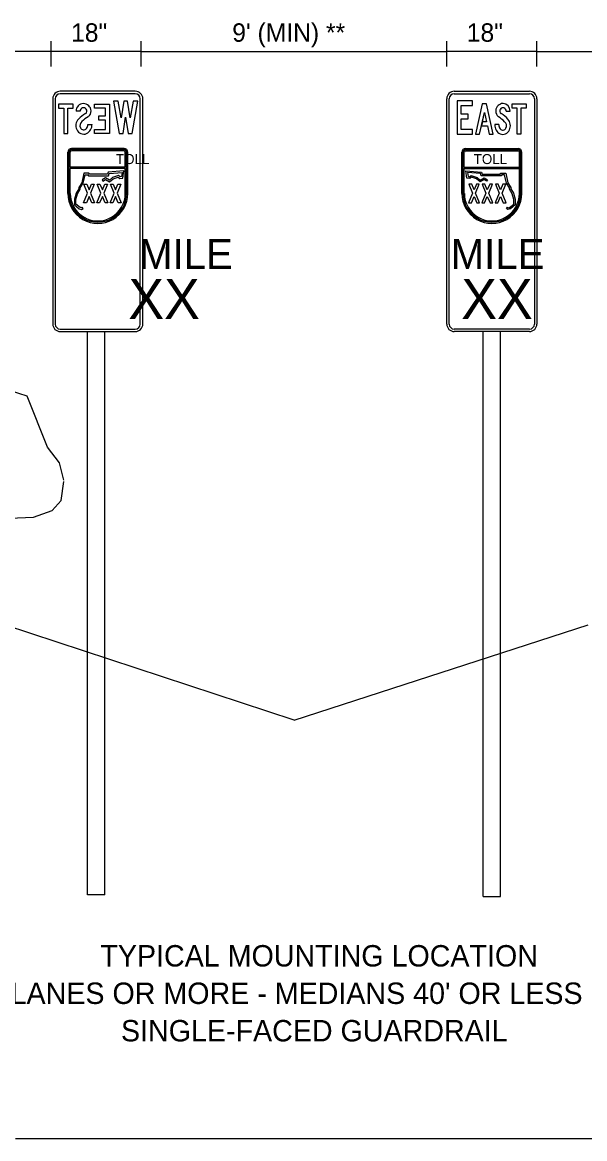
# Model space of a CAD drawing. Extents: x 57428 to 58066, y 11696 to 12105.
# Drawn here: x 57710.6 to 57796, y 11934.3 to 12103.9 of the extents above; entities that cross this region are included whole.
import ezdxf

# ---------------------------------------------------------------- set-up
doc = ezdxf.new("R2010")
doc.units = 0
for name, color, linetype in [('62', 7, 'Continuous'), ('DimLines_dp', 7, 'Continuous'), ('NonPlottingEle_dp', 7, 'Continuous'), ('SignPanel', 7, 'Continuous'), ('TextMisc', 7, 'Continuous'), ('TextTables', 7, 'Continuous'), ('XSGrdLine_ex', 7, 'Continuous')]:
    doc.layers.add(name, color=color, linetype=linetype)

msp = doc.modelspace()

# ---------------------------------------------------------------- linework, layer by layer
at = {"layer": '62'}
msp.add_lwpolyline([(57716.92, 12034.31), (57716.22, 12036.91), (57714.42, 12039.32), (57711.32, 12047.07), (57706.22, 12048.67), (57702.51, 12048.17), (57697.71, 12040.32), (57696.21, 12037.11), (57696.01, 12033.61), (57697.21, 12030.61), (57700.31, 12028.9), (57706.22, 12028.4), (57712.32, 12028.7), (57715.12, 12029.7), (57716.52, 12031.21), (57716.92, 12034.11)], dxfattribs=at)
at = {"layer": 'DimLines_dp'}
for p, q in [((57714.97, 12097.15), (57714.97, 12100.98)), ((57728.65, 12097.15), (57728.65, 12100.98)), ((57775.06, 12097.15), (57775.06, 12100.98)), ((57788.75, 12097.15), (57788.75, 12100.98)), ((57714.97, 12099.43), (57645.43, 12099.43)), ((57728.65, 12099.43), (57714.97, 12099.43)), ((57728.65, 12099.43), (57775.06, 12099.43)), ((57788.75, 12099.43), (57775.06, 12099.43)), ((57788.75, 12099.43), (57858.29, 12099.43))]:
    msp.add_line(p, q, dxfattribs=at)
at = {"layer": 'NonPlottingEle_dp'}
for p, q in [((57720.48, 12008.18), (57720.48, 12056.87)), ((57723.14, 12007.3), (57723.14, 12056.87)), ((57780.58, 12007.16), (57780.58, 12056.87)), ((57783.24, 12008.02), (57783.24, 12056.87)), ((57720.48, 11971.28), (57720.48, 12008.18)), ((57783.24, 11971.03), (57783.24, 12008.02)), ((57723.14, 11971.28), (57723.14, 12007.3)), ((57780.58, 11971.03), (57780.58, 12007.16)), ((57723.14, 11971.28), (57720.48, 11971.28)), ((57780.58, 11971.03), (57783.24, 11971.03))]:
    msp.add_line(p, q, dxfattribs=at)
at = {"layer": 'SignPanel'}
for p, q in [((57719.37, 12090.36), (57718.75, 12090.36)), ((57719.37, 12090.36), (57718.75, 12090.36)), ((57719.37, 12090.36), (57718.75, 12090.36)), ((57784.1, 12090.36), (57784.68, 12090.36)), ((57784.1, 12090.36), (57784.68, 12090.36)), ((57784.1, 12090.36), (57784.68, 12090.36)), ((57720.56, 12088.35), (57721.19, 12088.35)), ((57720.56, 12088.35), (57721.19, 12088.35)), ((57720.56, 12088.35), (57721.19, 12088.35)), ((57782.96, 12088.32), (57782.37, 12088.32)), ((57782.96, 12088.32), (57782.37, 12088.32)), ((57782.96, 12088.32), (57782.37, 12088.32)), ((57717.5, 12077.85), (57717.5, 12084.13)), ((57717.69, 12077.85), (57717.69, 12084.13)), ((57717.88, 12081.85), (57717.88, 12084.13)), ((57726.05, 12084.7), (57718.07, 12084.7)), ((57726.05, 12084.51), (57718.07, 12084.51)), ((57726.05, 12084.32), (57718.07, 12084.32)), ((57726.24, 12081.85), (57726.24, 12084.13)), ((57726.43, 12077.85), (57726.43, 12084.13)), ((57726.62, 12077.85), (57726.62, 12084.13)), ((57777.35, 12077.85), (57777.35, 12084.13)), ((57777.54, 12077.85), (57777.54, 12084.13)), ((57777.72, 12081.85), (57777.72, 12084.13)), ((57777.92, 12084.7), (57785.9, 12084.7)), ((57777.92, 12084.51), (57785.9, 12084.51)), ((57777.92, 12084.32), (57785.9, 12084.32)), ((57786.09, 12081.85), (57786.09, 12084.13)), ((57786.28, 12077.85), (57786.28, 12084.13)), ((57786.47, 12077.85), (57786.47, 12084.13)), ((57726.24, 12081.85), (57717.88, 12081.85)), ((57717.88, 12077.85), (57717.88, 12081.66)), ((57726.24, 12081.66), (57717.88, 12081.66)), ((57719.95, 12080.92), (57719.62, 12079.49)), ((57719.83, 12079.4), (57720.13, 12080.69)), ((57720.68, 12080.92), (57719.95, 12080.92)), ((57720.13, 12080.69), (57720.56, 12080.69)), ((57720.56, 12080.69), (57720.66, 12080.53)), ((57720.66, 12080.53), (57723.67, 12080.53)), ((57720.79, 12080.76), (57720.68, 12080.92)), ((57723.52, 12080.76), (57720.79, 12080.76)), ((57723.65, 12081.11), (57723.52, 12080.76)), ((57726.03, 12081.29), (57723.65, 12081.11)), ((57723.67, 12080.53), (57723.81, 12080.89)), ((57723.81, 12080.89), (57725.76, 12081.04)), ((57725.2, 12080.6), (57724.28, 12080.3)), ((57724.77, 12080.95), (57724.77, 12080.95)), ((57725.47, 12080.38), (57725.2, 12080.6)), ((57725.76, 12081.04), (57725.66, 12080.41)), ((57725.86, 12080.2), (57726.03, 12081.29)), ((57726.24, 12077.85), (57726.24, 12081.66)), ((57777.72, 12081.85), (57786.09, 12081.85)), ((57777.72, 12077.85), (57777.72, 12081.66)), ((57777.72, 12081.66), (57786.09, 12081.66)), ((57778.11, 12080.2), (57777.94, 12081.29)), ((57777.94, 12081.29), (57780.32, 12081.11)), ((57780.16, 12080.89), (57778.21, 12081.04)), ((57778.21, 12081.04), (57778.31, 12080.41)), ((57778.5, 12080.38), (57778.77, 12080.6)), ((57778.77, 12080.6), (57779.69, 12080.3)), ((57779.2, 12080.95), (57779.2, 12080.95)), ((57780.3, 12080.53), (57780.16, 12080.89)), ((57783.31, 12080.53), (57780.3, 12080.53)), ((57780.32, 12081.11), (57780.45, 12080.76)), ((57780.45, 12080.76), (57783.18, 12080.76)), ((57783.18, 12080.76), (57783.29, 12080.92)), ((57783.29, 12080.92), (57784.02, 12080.92)), ((57783.41, 12080.69), (57783.31, 12080.53)), ((57783.84, 12080.69), (57783.41, 12080.69)), ((57784.14, 12079.4), (57783.84, 12080.69)), ((57784.02, 12080.92), (57784.35, 12079.49)), ((57786.09, 12077.85), (57786.09, 12081.66)), ((57719.62, 12079.49), (57719.16, 12078.76)), ((57719.39, 12078.69), (57719.83, 12079.4)), ((57723.22, 12080.24), (57722.72, 12079.9)), ((57722.72, 12079.9), (57722.85, 12079.71)), ((57722.85, 12079.71), (57723.23, 12079.97)), ((57723.83, 12079.88), (57723.22, 12080.24)), ((57723.23, 12079.97), (57723.86, 12079.6)), ((57724.28, 12080.3), (57723.83, 12079.88)), ((57723.86, 12079.6), (57724.4, 12080.1)), ((57724.4, 12080.1), (57725.15, 12080.34)), ((57725.15, 12080.34), (57725.4, 12080.15)), ((57725.4, 12080.15), (57725.86, 12080.2)), ((57725.66, 12080.41), (57725.47, 12080.38)), ((57778.56, 12080.15), (57778.11, 12080.2)), ((57778.31, 12080.41), (57778.5, 12080.38)), ((57778.81, 12080.34), (57778.56, 12080.15)), ((57779.57, 12080.1), (57778.81, 12080.34)), ((57780.11, 12079.6), (57779.57, 12080.1)), ((57779.69, 12080.3), (57780.14, 12079.88)), ((57780.74, 12079.97), (57780.11, 12079.6)), ((57780.14, 12079.88), (57780.75, 12080.24)), ((57781.12, 12079.71), (57780.74, 12079.97)), ((57780.75, 12080.24), (57781.25, 12079.9)), ((57781.25, 12079.9), (57781.12, 12079.71)), ((57784.58, 12078.69), (57784.14, 12079.4)), ((57784.35, 12079.49), (57784.81, 12078.76)), ((57718.75, 12077.9), (57718.5, 12076.98)), ((57718.73, 12076.95), (57718.97, 12077.81)), ((57719.16, 12078.57), (57718.75, 12077.9)), ((57718.97, 12077.81), (57719.39, 12078.51)), ((57719.16, 12078.76), (57719.16, 12078.57)), ((57719.39, 12078.51), (57719.39, 12078.69)), ((57784.58, 12078.51), (57784.58, 12078.69)), ((57785, 12077.81), (57784.58, 12078.51)), ((57784.81, 12078.76), (57784.81, 12078.57)), ((57784.81, 12078.57), (57785.22, 12077.9)), ((57785.24, 12076.95), (57785, 12077.81)), ((57785.22, 12077.9), (57785.47, 12076.98)), ((57718.5, 12076.98), (57718.5, 12076.12)), ((57718.5, 12076.12), (57719.25, 12075.5)), ((57718.73, 12076.22), (57718.73, 12076.95)), ((57719.36, 12075.71), (57718.73, 12076.22)), ((57719.25, 12075.5), (57719.61, 12075.41)), ((57719.56, 12075.66), (57719.36, 12075.71)), ((57719.71, 12075.76), (57719.56, 12075.66)), ((57719.61, 12075.41), (57719.84, 12075.57)), ((57719.84, 12075.57), (57719.71, 12075.76)), ((57784.13, 12075.57), (57784.26, 12075.76)), ((57784.36, 12075.41), (57784.13, 12075.57)), ((57784.26, 12075.76), (57784.41, 12075.66)), ((57784.72, 12075.5), (57784.36, 12075.41)), ((57784.41, 12075.66), (57784.61, 12075.71)), ((57784.61, 12075.71), (57785.24, 12076.22)), ((57785.47, 12076.12), (57784.72, 12075.5)), ((57785.24, 12076.22), (57785.24, 12076.95)), ((57785.47, 12076.98), (57785.47, 12076.12))]:
    msp.add_line(p, q, dxfattribs=at)
for points in [[(57727.76, 12093.37), (57716.36, 12093.37)], [(57727.76, 12092.99), (57716.36, 12092.99)], [(57776.2, 12093.37), (57787.61, 12093.37)], [(57776.2, 12092.99), (57787.61, 12092.99)], [(57715.22, 12092.23), (57715.22, 12058.01)], [(57715.6, 12092.23), (57715.6, 12058.01)], [(57728.52, 12058.01), (57728.52, 12092.23)], [(57728.9, 12058.01), (57728.9, 12092.23)], [(57775.06, 12058.01), (57775.06, 12092.23)], [(57775.44, 12058.01), (57775.44, 12092.23)], [(57788.37, 12092.23), (57788.37, 12058.01)], [(57788.75, 12092.23), (57788.75, 12058.01)], [(57716.36, 12057.25), (57727.76, 12057.25)], [(57716.36, 12056.87), (57727.76, 12056.87)], [(57787.61, 12057.25), (57776.2, 12057.25)], [(57787.61, 12056.87), (57776.2, 12056.87)]]:
    msp.add_lwpolyline(points, dxfattribs=at)
for points in [[(57717.51, 12090.81), (57718.33, 12090.81), (57718.33, 12091.44), (57716.07, 12091.44), (57716.07, 12090.81), (57716.89, 12090.81), (57716.89, 12086.94), (57717.51, 12086.94)], [(57717.51, 12090.81), (57718.33, 12090.81), (57718.33, 12091.44), (57716.07, 12091.44), (57716.07, 12090.81), (57716.89, 12090.81), (57716.89, 12086.94), (57717.51, 12086.94)], [(57717.51, 12090.81), (57718.33, 12090.81), (57718.33, 12091.44), (57716.07, 12091.44), (57716.07, 12090.81), (57716.89, 12090.81), (57716.89, 12086.94), (57717.51, 12086.94)], [(57723.21, 12087.57), (57723.21, 12089.01), (57722.24, 12089.01), (57722.24, 12089.64), (57723.21, 12089.64), (57723.21, 12090.81), (57721.57, 12090.81), (57721.57, 12091.44), (57723.84, 12091.44), (57723.84, 12086.94), (57721.57, 12086.94), (57721.57, 12087.57)], [(57723.21, 12087.57), (57723.21, 12089.01), (57722.24, 12089.01), (57722.24, 12089.64), (57723.21, 12089.64), (57723.21, 12090.81), (57721.57, 12090.81), (57721.57, 12091.44), (57723.84, 12091.44), (57723.84, 12086.94), (57721.57, 12086.94), (57721.57, 12087.57)], [(57723.21, 12087.57), (57723.21, 12089.01), (57722.24, 12089.01), (57722.24, 12089.64), (57723.21, 12089.64), (57723.21, 12090.81), (57721.57, 12090.81), (57721.57, 12091.44), (57723.84, 12091.44), (57723.84, 12086.94), (57721.57, 12086.94), (57721.57, 12087.57)], [(57727, 12089.33), (57726.59, 12091.89), (57725.99, 12091.89), (57725.59, 12089.33), (57725.13, 12091.89), (57724.44, 12091.89), (57725.31, 12086.94), (57725.9, 12086.94), (57726.29, 12089.42), (57726.68, 12086.94), (57727.27, 12086.94), (57728.14, 12091.89), (57727.45, 12091.89)], [(57727, 12089.33), (57726.59, 12091.89), (57725.99, 12091.89), (57725.59, 12089.33), (57725.13, 12091.89), (57724.44, 12091.89), (57725.31, 12086.94), (57725.9, 12086.94), (57726.29, 12089.42), (57726.68, 12086.94), (57727.27, 12086.94), (57728.14, 12091.89), (57727.45, 12091.89)], [(57727, 12089.33), (57726.59, 12091.89), (57725.99, 12091.89), (57725.59, 12089.33), (57725.13, 12091.89), (57724.44, 12091.89), (57725.31, 12086.94), (57725.9, 12086.94), (57726.29, 12089.42), (57726.68, 12086.94), (57727.27, 12086.94), (57728.14, 12091.89), (57727.45, 12091.89)], [(57777.27, 12087.59), (57777.27, 12089.21), (57778.29, 12089.21), (57778.29, 12089.92), (57777.27, 12089.92), (57777.27, 12091.24), (57778.99, 12091.24), (57778.99, 12091.95), (57776.62, 12091.95), (57776.62, 12086.88), (57778.99, 12086.88), (57778.99, 12087.59)], [(57777.27, 12087.59), (57777.27, 12089.21), (57778.29, 12089.21), (57778.29, 12089.92), (57777.27, 12089.92), (57777.27, 12091.24), (57778.99, 12091.24), (57778.99, 12091.95), (57776.62, 12091.95), (57776.62, 12086.88), (57778.99, 12086.88), (57778.99, 12087.59)], [(57777.27, 12087.59), (57777.27, 12089.21), (57778.29, 12089.21), (57778.29, 12089.92), (57777.27, 12089.92), (57777.27, 12091.24), (57778.99, 12091.24), (57778.99, 12091.95), (57776.62, 12091.95), (57776.62, 12086.88), (57778.99, 12086.88), (57778.99, 12087.59)], [(57781.24, 12088.11), (57781.51, 12086.88), (57782.11, 12086.88), (57781.09, 12091.46), (57780.46, 12091.46), (57779.44, 12086.88), (57780.05, 12086.88), (57780.32, 12088.11)], [(57780.47, 12088.75), (57780.32, 12088.11), (57781.24, 12088.11), (57781.51, 12086.88), (57782.11, 12086.88), (57781.09, 12091.46), (57780.46, 12091.46), (57779.44, 12086.88), (57780.05, 12086.88), (57780.78, 12090.16), (57781.09, 12088.75)], [(57780.47, 12088.75), (57780.32, 12088.11), (57781.24, 12088.11), (57781.51, 12086.88), (57782.11, 12086.88), (57781.09, 12091.46), (57780.46, 12091.46), (57779.44, 12086.88), (57780.05, 12086.88), (57780.78, 12090.16), (57781.09, 12088.75)], [(57785.75, 12090.82), (57784.97, 12090.82), (57784.97, 12091.46), (57787.11, 12091.46), (57787.11, 12090.82), (57786.33, 12090.82), (57786.33, 12086.88), (57785.75, 12086.88)], [(57785.75, 12090.82), (57784.97, 12090.82), (57784.97, 12091.46), (57787.11, 12091.46), (57787.11, 12090.82), (57786.33, 12090.82), (57786.33, 12086.88), (57785.75, 12086.88)], [(57785.75, 12090.82), (57784.97, 12090.82), (57784.97, 12091.46), (57787.11, 12091.46), (57787.11, 12090.82), (57786.33, 12090.82), (57786.33, 12086.88), (57785.75, 12086.88)], [(57780.78, 12090.16), (57781.09, 12088.75), (57780.47, 12088.75)], [(57721.14, 12076.44), (57720.73, 12077.41), (57720.32, 12076.44), (57719.9, 12076.44), (57720.52, 12077.92), (57719.95, 12079.29), (57720.37, 12079.29), (57720.73, 12078.43), (57721.09, 12079.29), (57721.52, 12079.29), (57720.95, 12077.92), (57721.57, 12076.44)], [(57723.16, 12076.44), (57722.75, 12077.41), (57722.34, 12076.44), (57721.91, 12076.44), (57722.53, 12077.92), (57721.96, 12079.29), (57722.39, 12079.29), (57722.75, 12078.43), (57723.11, 12079.29), (57723.53, 12079.29), (57722.96, 12077.92), (57723.58, 12076.44)], [(57725.17, 12076.44), (57724.76, 12077.41), (57724.36, 12076.44), (57723.93, 12076.44), (57724.55, 12077.92), (57723.98, 12079.29), (57724.41, 12079.29), (57724.76, 12078.43), (57725.12, 12079.29), (57725.55, 12079.29), (57724.98, 12077.92), (57725.6, 12076.44)], [(57778.8, 12076.44), (57779.21, 12077.41), (57779.61, 12076.44), (57780.04, 12076.44), (57779.42, 12077.92), (57779.99, 12079.29), (57779.56, 12079.29), (57779.21, 12078.43), (57778.85, 12079.29), (57778.42, 12079.29), (57778.99, 12077.92), (57778.37, 12076.44)], [(57780.81, 12076.44), (57781.22, 12077.41), (57781.63, 12076.44), (57782.06, 12076.44), (57781.43, 12077.92), (57782.01, 12079.29), (57781.58, 12079.29), (57781.22, 12078.43), (57780.86, 12079.29), (57780.44, 12079.29), (57781.01, 12077.92), (57780.39, 12076.44)], [(57782.83, 12076.44), (57783.24, 12077.41), (57783.65, 12076.44), (57784.07, 12076.44), (57783.45, 12077.92), (57784.02, 12079.29), (57783.6, 12079.29), (57783.24, 12078.43), (57782.88, 12079.29), (57782.45, 12079.29), (57783.02, 12077.92), (57782.4, 12076.44)]]:
    msp.add_lwpolyline(points, close=True, dxfattribs=at)
for centre, radius, start, end in [((57716.36, 12092.23), 1.14, 90, 180), ((57716.36, 12092.23), 0.76, 90, 180), ((57727.76, 12092.23), 1.14, 0, 90), ((57727.76, 12092.23), 0.76, 0, 90), ((57776.2, 12092.23), 1.14, 90, 180), ((57776.2, 12092.23), 0.76, 90, 180), ((57787.61, 12092.23), 1.14, 0, 90), ((57787.61, 12092.23), 0.76, 0, 90), ((57716.36, 12058.01), 1.14, 180, 270), ((57716.36, 12058.01), 0.76, 180, 270), ((57727.76, 12058.01), 1.14, 270, 0), ((57727.76, 12058.01), 0.76, 270, 0), ((57776.2, 12058.01), 1.14, 180, 270), ((57776.2, 12058.01), 0.76, 180, 270), ((57787.61, 12058.01), 1.14, 270, 360), ((57787.61, 12058.01), 0.76, 270, 360)]:
    msp.add_arc(centre, radius, start, end, dxfattribs=at)
for centre, major_axis, ratio, start_param, end_param in [((57719.9, 12090.33), (0, -1.17), 0.981197, 1.634182, 4.688511), ((57719.9, 12090.33), (0, -1.17), 0.981197, 1.634182, 4.688511), ((57719.9, 12090.33), (0, -1.17), 0.981197, 1.634182, 4.688511), ((57719.91, 12090.32), (0, -0.55), 0.981197, 2.28404, 4.637874), ((57719.91, 12090.32), (0, -0.55), 0.981197, 2.28404, 4.637874), ((57719.91, 12090.32), (0, -0.55), 0.981197, 2.28404, 4.637874), ((57783.59, 12090.33), (0, 1.19), 0.91923, 4.736267, 7.790596), ((57783.59, 12090.33), (0, 1.19), 0.91923, 4.736267, 7.790596), ((57783.59, 12090.33), (0, 1.19), 0.91923, 4.736267, 7.790596), ((57783.59, 12090.32), (0, 0.558), 0.91923, 4.786904, 7.140738), ((57783.59, 12090.32), (0, 0.558), 0.91923, 4.786904, 7.140738), ((57783.59, 12090.32), (0, 0.558), 0.91923, 4.786904, 7.140738), ((57720.1, 12088.17), (0, -1.4), 0.981197, 3.939023, 5.163791), ((57720.1, 12088.17), (0, -1.4), 0.981197, 3.939023, 5.163791), ((57720.1, 12088.17), (0, -1.4), 0.981197, 3.939023, 5.163791), ((57722.22, 12086.2), (0, -4.32), 0.981197, 3.642536, 3.961892), ((57722.22, 12086.2), (0, -4.32), 0.981197, 3.642536, 3.961892), ((57722.22, 12086.2), (0, -4.32), 0.981197, 3.642536, 3.961892), ((57722.75, 12085.51), (0, -4.56), 0.981197, 3.63779, 3.909641), ((57722.75, 12085.51), (0, -4.56), 0.981197, 3.63779, 3.909641), ((57722.75, 12085.51), (0, -4.56), 0.981197, 3.63779, 3.909641), ((57719.97, 12090.39), (0, -0.453), 0.981197, 0.484634, 2.267813), ((57719.97, 12090.39), (0, -0.453), 0.981197, 0.484634, 2.267813), ((57719.97, 12090.39), (0, -0.453), 0.981197, 0.484634, 2.267813), ((57720.02, 12090.37), (0, -1.05), 0.981197, 0.629826, 1.606762), ((57720.02, 12090.37), (0, -1.05), 0.981197, 0.629826, 1.606762), ((57720.02, 12090.37), (0, -1.05), 0.981197, 0.629826, 1.606762), ((57783.48, 12090.37), (0, 1.07), 0.91923, 1.534831, 2.511766), ((57783.48, 12090.37), (0, 1.07), 0.91923, 1.534831, 2.511766), ((57783.48, 12090.37), (0, 1.07), 0.91923, 1.534831, 2.511766), ((57780.88, 12085.43), (0, 4.63), 0.91923, 5.515137, 5.786988), ((57780.88, 12085.43), (0, 4.63), 0.91923, 5.515137, 5.786988), ((57780.88, 12085.43), (0, 4.63), 0.91923, 5.515137, 5.786988), ((57783.52, 12090.39), (0, 0.46), 0.91923, 0.87378, 2.656959), ((57783.52, 12090.39), (0, 0.46), 0.91923, 0.87378, 2.656959), ((57783.52, 12090.39), (0, 0.46), 0.91923, 0.87378, 2.656959), ((57781.39, 12086.13), (0, 4.39), 0.91923, 5.462886, 5.782242), ((57781.39, 12086.13), (0, 4.39), 0.91923, 5.462886, 5.782242), ((57781.39, 12086.13), (0, 4.39), 0.91923, 5.462886, 5.782242), ((57783.41, 12088.13), (0, 1.42), 0.91923, 4.260987, 5.485755), ((57783.41, 12088.13), (0, 1.42), 0.91923, 4.260987, 5.485755), ((57783.41, 12088.13), (0, 1.42), 0.91923, 4.260987, 5.485755), ((57719.94, 12088.1), (0, -1.23), 0.981197, 5.173086, 6.638731), ((57719.94, 12088.1), (0, -1.23), 0.981197, 5.173086, 6.638731), ((57719.94, 12088.1), (0, -1.23), 0.981197, 5.173086, 6.638731), ((57720.11, 12088.17), (0, -0.78), 0.981197, 3.79238, 5.170369), ((57720.11, 12088.17), (0, -0.78), 0.981197, 3.79238, 5.170369), ((57720.11, 12088.17), (0, -0.78), 0.981197, 3.79238, 5.170369), ((57719.92, 12088.09), (0, -0.572), 0.981197, 5.194718, 7.162991), ((57719.92, 12088.09), (0, -0.572), 0.981197, 5.194718, 7.162991), ((57719.92, 12088.09), (0, -0.572), 0.981197, 5.194718, 7.162991), ((57719.68, 12088.31), (0, -0.897), 0.981197, 0.859453, 1.616836), ((57719.68, 12088.31), (0, -0.897), 0.981197, 0.859453, 1.616836), ((57719.68, 12088.31), (0, -0.897), 0.981197, 0.859453, 1.616836), ((57719.74, 12088.29), (0, -1.47), 0.981197, 0.439911, 1.615229), ((57719.74, 12088.29), (0, -1.47), 0.981197, 0.439911, 1.615229), ((57719.74, 12088.29), (0, -1.47), 0.981197, 0.439911, 1.615229), ((57783.74, 12088.25), (0, 1.5), 0.91923, 1.526364, 2.701682), ((57783.74, 12088.25), (0, 1.5), 0.91923, 1.526364, 2.701682), ((57783.74, 12088.25), (0, 1.5), 0.91923, 1.526364, 2.701682), ((57783.8, 12088.28), (0, 0.911), 0.91923, 1.524757, 2.28214), ((57783.8, 12088.28), (0, 0.911), 0.91923, 1.524757, 2.28214), ((57783.8, 12088.28), (0, 0.911), 0.91923, 1.524757, 2.28214), ((57783.56, 12088.07), (0, 1.24), 0.91923, 2.786047, 4.251692), ((57783.56, 12088.07), (0, 1.24), 0.91923, 2.786047, 4.251692), ((57783.56, 12088.07), (0, 1.24), 0.91923, 2.786047, 4.251692), ((57783.58, 12088.05), (0, 0.581), 0.91923, 2.261787, 4.23006), ((57783.58, 12088.05), (0, 0.581), 0.91923, 2.261787, 4.23006), ((57783.58, 12088.05), (0, 0.581), 0.91923, 2.261787, 4.23006), ((57783.4, 12088.13), (0, 0.792), 0.91923, 4.254409, 5.632398), ((57783.4, 12088.13), (0, 0.792), 0.91923, 4.254409, 5.632398), ((57783.4, 12088.13), (0, 0.792), 0.91923, 4.254409, 5.632398), ((57718.07, 12084.13), (0, 0.57), 0.9997, 0, 1.570796), ((57718.07, 12084.13), (0, 0.38), 0.9997, 0, 1.570796), ((57718.07, 12084.13), (0, 0.19), 0.9997, 0, 1.570796), ((57726.05, 12084.13), (0, 0.57), 0.9997, 4.712389, 6.283185), ((57726.05, 12084.13), (0, 0.38), 0.9997, 4.712389, 6.283185), ((57726.05, 12084.13), (0, 0.19), 0.9997, 4.712389, 6.283185), ((57777.92, 12084.13), (0, 0.57), 0.9997, 0, 1.570796), ((57777.92, 12084.13), (0, 0.38), 0.9997, 0, 1.570796), ((57777.92, 12084.13), (0, 0.19), 0.9997, 0, 1.570796), ((57785.9, 12084.13), (0, 0.57), 0.9997, 4.712389, 6.283185), ((57785.9, 12084.13), (0, 0.38), 0.9997, 4.712389, 6.283185), ((57785.9, 12084.13), (0, 0.19), 0.9997, 4.712389, 6.283185), ((57722.06, 12077.86), (0, 4.56), 0.9997, 1.570796, 4.712389), ((57722.06, 12077.86), (0, 4.37), 0.9997, 1.570796, 4.712389), ((57722.06, 12077.86), (0, 4.18), 0.9997, 1.570796, 4.712389), ((57781.91, 12077.86), (0, -4.56), 0.9997, 4.712389, 7.853982), ((57781.91, 12077.86), (0, -4.37), 0.9997, 4.712389, 7.853982), ((57781.91, 12077.86), (0, -4.18), 0.9997, 4.712389, 7.853982)]:
    msp.add_ellipse(centre, major_axis=major_axis, ratio=ratio, start_param=start_param, end_param=end_param, dxfattribs=at)
at = {"layer": 'TextMisc'}
msp.add_line((58065.89, 11934.25), (57709.55, 11934.25), dxfattribs=at)
at = {"layer": 'XSGrdLine_ex'}
for q in [(57707.87, 12012.33), (57796.52, 12012.33)]:
    msp.add_line((57751.86, 11997.83), q, dxfattribs=at)

# ---------------------------------------------------------------- texts
at = {"layer": 'DimLines_dp'}
for s, p in [('18"', (57718, 12100.9)), ("9' (MIN) **", (57742.48, 12100.9)), ('18"', (57778.1, 12100.9))]:
    msp.add_text(s, height=2.8, dxfattribs=at).set_placement(p)
at = {"layer": 'SignPanel'}
for s, height, p in [('TOLL', 1.519, (57724.82, 12082.32)), ('TOLL', 1.519, (57779.15, 12082.32)), ('MILE', 4.562, (57728.32, 12066.37)), ('MILE', 4.562, (57775.65, 12066.37)), ('XX', 6.083, (57726.7, 12058.8)), ('XX', 6.083, (57777.26, 12058.8))]:
    msp.add_text(s, height=height, dxfattribs=at).set_placement(p)
at = {"layer": 'TextTables'}
for s, p in [('TYPICAL MOUNTING LOCATION', (57722.45, 11960.41)), ("6 LANES OR MORE - MEDIANS 40' OR LESS", (57705.19, 11954.72)), ('SINGLE-FACED GUARDRAIL', (57725.58, 11949.03))]:
    msp.add_text(s, height=3.2524, dxfattribs=at).set_placement(p)

doc.saveas('drawing.dxf')
